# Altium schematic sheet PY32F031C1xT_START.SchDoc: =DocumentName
size A3; Revision: V2.0; SheetNumber: 2; SheetTotal: 2
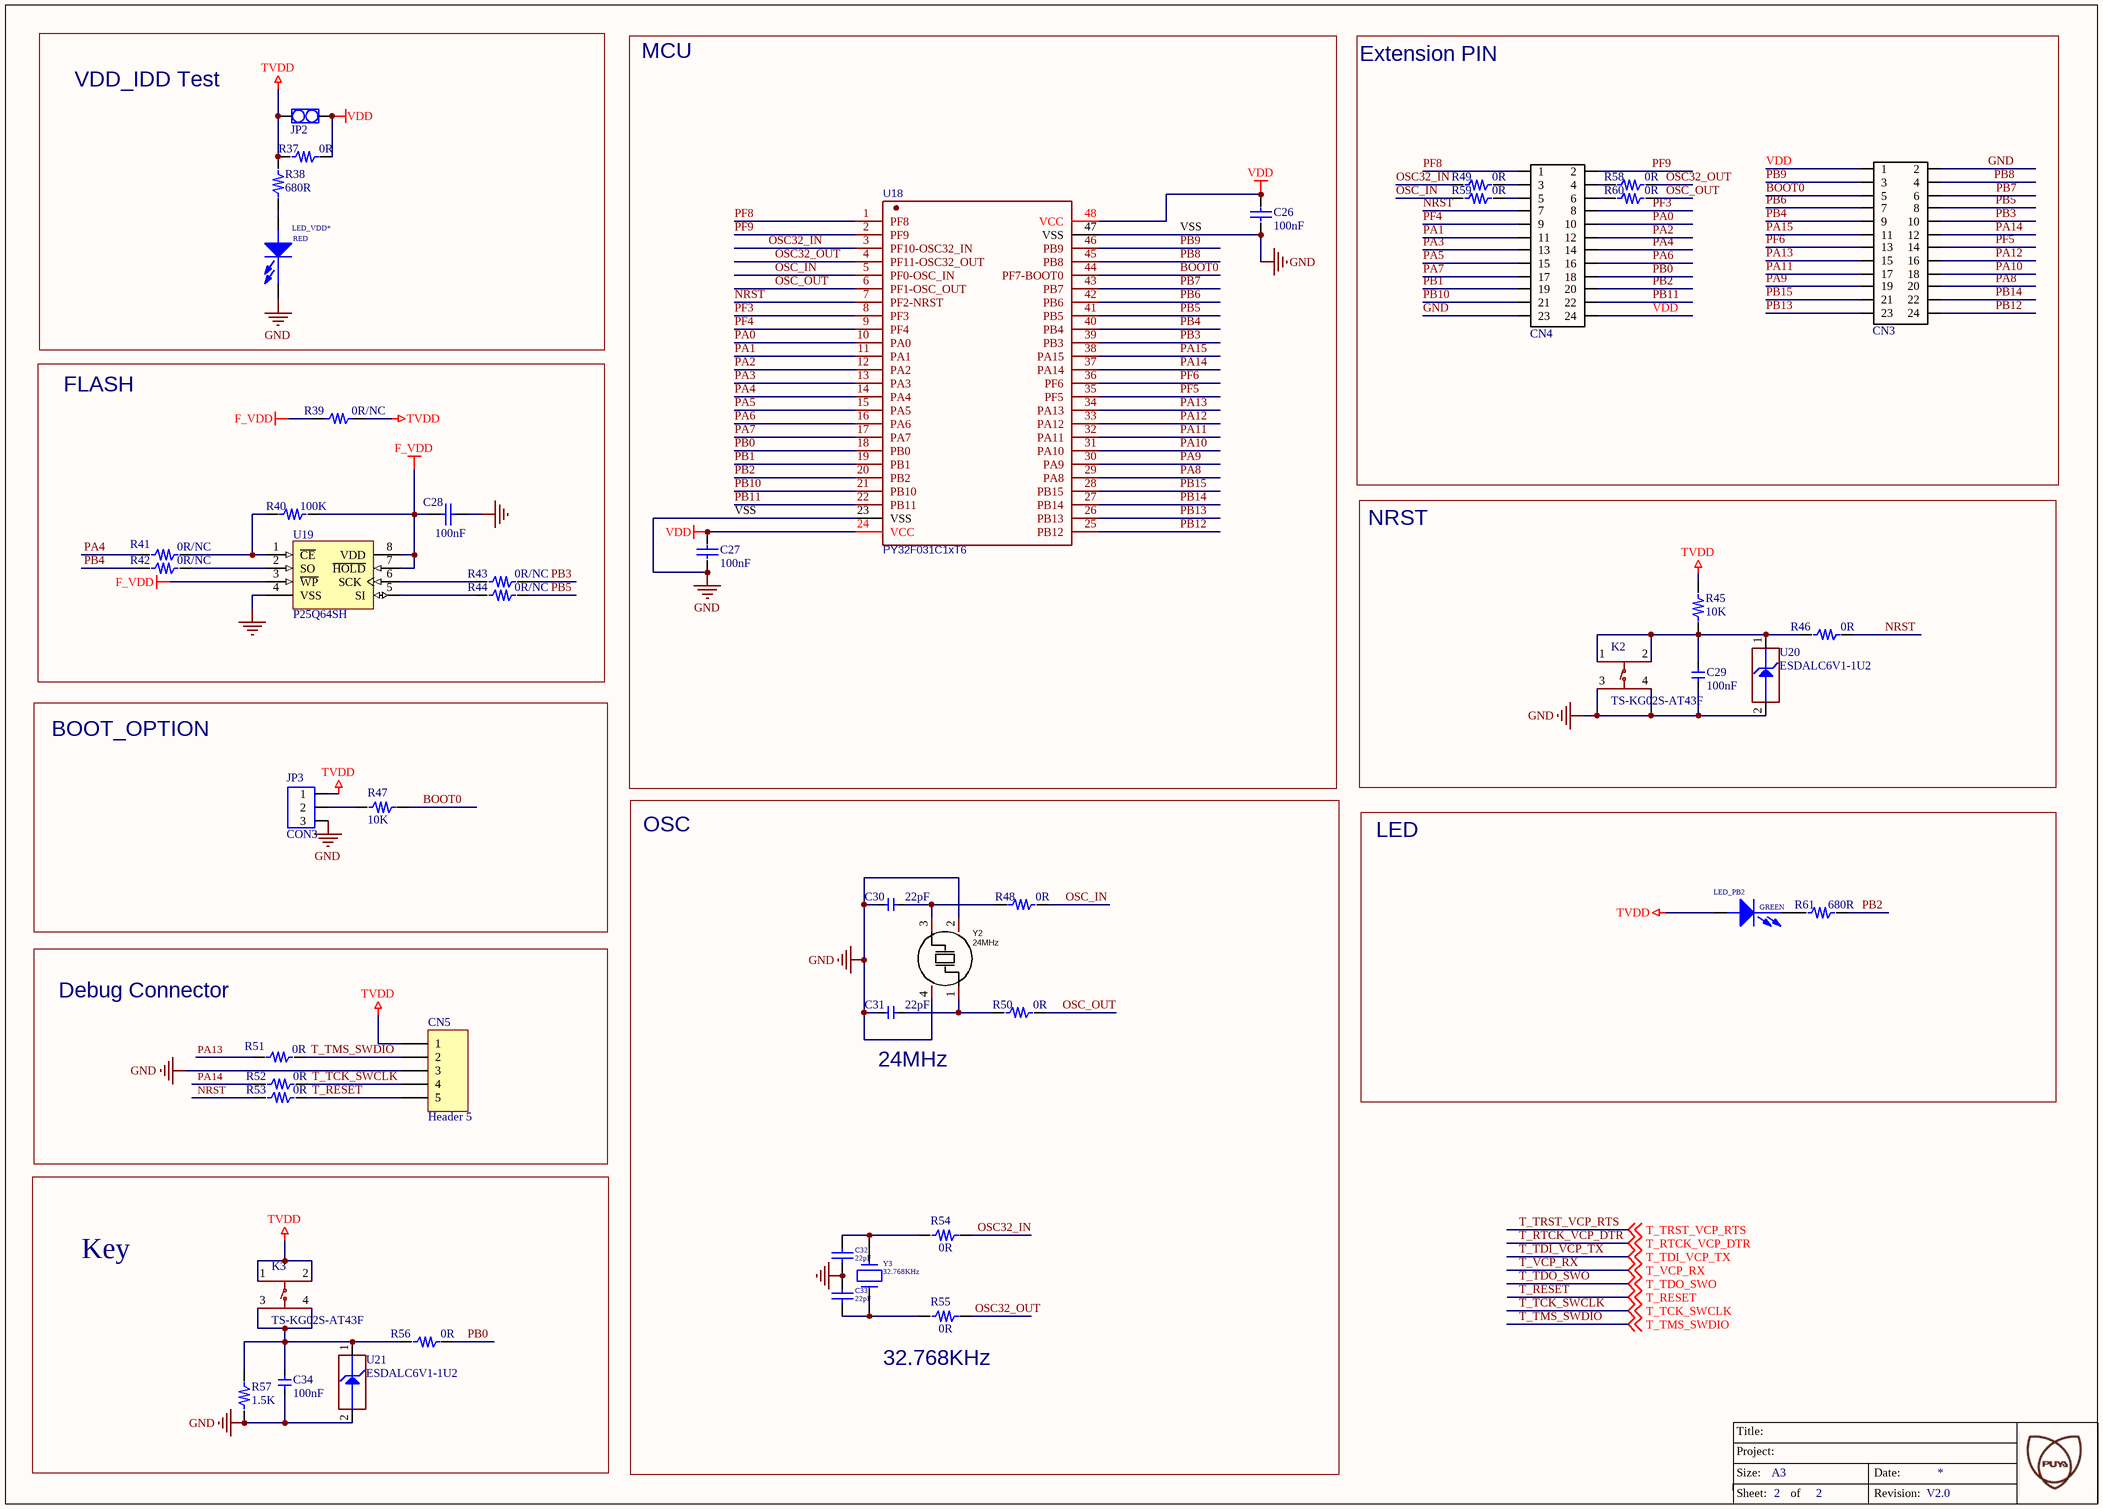
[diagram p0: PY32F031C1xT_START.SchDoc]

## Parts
C26  100nF  [C0603]
C27  100nF  [C0603]
C28  100nF  [C0603]
C29  100nF  [C0603]
C30  22pF  [C0603]
C31  22pF  [C0603]
C32  22pF  [C0603]
C33  22pF  [C0603]
C34  100nF  [C0603]
CN3  CON 2X12  [CON 2X12]  (value not drawn)
CN4  CON 2X12  [CON 2X12]  (value not drawn)
CN5  Header 5  [HDR1X5]
JP2  CON2  [CON2]  (value not drawn)
JP3  CON3  [CON3]
K2  TS-KG02S-AT43F  [SW-SMD_4P-L6.0-W6.0-P4.50-LS8.5]
K3  TS-KG02S-AT43F  [SW-SMD_4P-L6.0-W6.0-P4.50-LS8.5]
LED_PB2  GREEN  [0603_LED]
LED_VDD*  RED  [0603_LED]
R37  0R  [JP2_SMD]
R38  680R  [R0603]
R39  0R/NC  [JP2_SMD]
R40  100K  [R0603]
R41  0R/NC  [JP2_SMD]
R42  0R/NC  [JP2_SMD]
R43  0R/NC  [JP2_SMD]
R44  0R/NC  [JP2_SMD]
R45  10K  [R0603]
R46  0R  [JP2_SMD]
R47  10K  [R0603]
R48  0R  [JP2_SMD]
R49  0R  [JP2_SMD]
R50  0R  [JP2_SMD]
R51  0R  [JP2_SMD]
R52  0R  [JP2_SMD]
R53  0R  [JP2_SMD]
R54  0R  [JP2_SMD]
R55  0R  [JP2_SMD]
R56  0R  [JP2_SMD]
R57  1.5K  [R0603]
R58  0R  [JP2_SMD]
R59  0R  [JP2_SMD]
R60  0R  [JP2_SMD]
R61  680R  [R0603]
U18  PY32F031C1xT6  [LQFP-48_L7.0-W7.0-P0.50-LS9.0-BL]
U19  P25Q64SH  [SOP-8P]
U20  ESDALC6V1-1U2  [ESD_ST0201]
U21  ESDALC6V1-1U2  [ESD_ST0201]
Y2  24MHz  [CRYSTAL-SMD_4P-L3.2-W2.5-BL]
Y3  32.768KHz  [CRYSTAL-SMD_L3.2-W1.5-1]

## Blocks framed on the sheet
VDD_IDD Test: JP2 LED_VDD* R37 R38
MCU: C26 C27 U18
Extension PIN: CN3 CN4 R49 R58-R60
FLASH: C28 R39-R44 U19
NRST: C29 K2 R45 R46 U20
BOOT_OPTION: JP3 R47
LED: LED_PB2 R61
Debug Connector: CN5 R51-R53
Key: C34 K3 R56 R57 U21

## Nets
F_VDD: C28.2 R39.2 R40.2 U19.3(~{WP}) U19.7(~{HOLD}) U19.8(VDD)
GND: C26.2 C27.1 C28.1 C29.1 C30.1 C31.1 C32.2 C33.1 C34.1 CN3.2 CN4.23 CN5.3 JP3.3 K2.3 K2.4 LED_VDD*.2(CATHODE) R57.1 U18.23(VSS) U18.47(VSS) U19.4(VSS) U20.2(GND) U21.2(GND) Y2.2(GND) Y2.4(GND)  [also labelled VSS]
TVDD: CN5.1 JP2.1 JP3.1 K3.1 K3.2 LED_PB2.1(ANODE) R37.1 R38.2 R39.1 R45.1
VDD: C26.1 C27.2 CN3.1 CN4.24 JP2.2 R37.2 U18.24(VCC) U18.48(VCC)
BOOT0: CN3.5 R47.2 U18.44(PF7-BOOT0)
NRST: CN4.7 R46.2 R53.2 U18.7(PF2-NRST)
OSC32_IN: R49.1 R54.1 U18.3(PF10-OSC32_IN)
OSC32_OUT: R55.1 R58.1 U18.4(PF11-OSC32_OUT)
OSC_IN: R48.2 R59.1 U18.5(PF0-OSC_IN)
OSC_OUT: R50.2 R60.1 U18.6(PF1-OSC_OUT)
PA0: CN4.10 U18.10(PA0)
PA1: CN4.11 U18.11(PA1)
PA2: CN4.12 U18.12(PA2)
PA3: CN4.13 U18.13(PA3)
PA4: CN4.14 R41.2 U18.14(PA4)
PA5: CN4.15 U18.15(PA5)
PA6: CN4.16 U18.16(PA6)
PA7: CN4.17 U18.17(PA7)
PA8: CN3.20 U18.29(PA8)
PA9: CN3.19 U18.30(PA9)
PA10: CN3.18 U18.31(PA10)
PA11: CN3.17 U18.32(PA11)
PA12: CN3.16 U18.33(PA12)
PA13: CN3.15 R51.2 U18.34(PA13)
PA14: CN3.12 R52.2 U18.37(PA14)
PA15: CN3.11 U18.38(PA15)
PB0: CN4.18 R56.2 U18.18(PB0)
PB1: CN4.19 U18.19(PB1)
PB2: CN4.20 R61.2 U18.20(PB2)
PB3: CN3.10 R43.1 U18.39(PB3)
PB4: CN3.9 R42.2 U18.40(PB4)
PB5: CN3.8 R44.1 U18.41(PB5)
PB6: CN3.7 U18.42(PB6)
PB7: CN3.6 U18.43(PB7)
PB8: CN3.4 U18.45(PB8)
PB9: CN3.3 U18.46(PB9)
PB10: CN4.21 U18.21(PB10)
PB11: CN4.22 U18.22(PB11)
PB12: CN3.24 U18.25(PB12)
PB13: CN3.23 U18.26(PB13)
PB14: CN3.22 U18.27(PB14)
PB15: CN3.21 U18.28(PB15)
PF3: CN4.8 U18.8(PF3)
PF4: CN4.9 U18.9(PF4)
PF5: CN3.14 U18.35(PF5)
PF6: CN3.13 U18.36(PF6)
PF8: CN4.1 U18.1(PF8)
PF9: CN4.2 U18.2(PF9)
T_RESET: CN5.5 R53.1 ; off-sheet T_RESET
T_TCK_SWCLK: CN5.4 R52.1 ; off-sheet T_TCK_SWCLK
T_TMS_SWDIO: CN5.2 R51.1 ; off-sheet T_TMS_SWDIO
NetC29_2: C29.2 K2.1 K2.2 R45.2 R46.1 U20.1(IO1)
NetC30_2: C30.2 R48.1 Y2.3(OSC2)
NetC31_2: C31.2 R50.1 Y2.1(OSC1)
NetC32_1: C32.1 R54.2 Y3.2
NetC33_2: C33.2 R55.2 Y3.1
NetC34_2: C34.2 K3.3 K3.4 R56.1 R57.2 U21.1(IO1)
NetCN4_3: CN4.3 R49.2
NetCN4_4: CN4.4 R58.2
NetCN4_5: CN4.5 R59.2
NetCN4_6: CN4.6 R60.2
NetJP3_2: JP3.2 R47.1
NetLED_PB2_2: LED_PB2.2(CATHODE) R61.1
NetLED_VDD*_1: LED_VDD*.1(ANODE) R38.1
NetR40_1: R40.1 R41.1 U19.1(~{CE})
NetR42_1: R42.1 U19.2(SO)
NetR43_2: R43.2 U19.6(SCK)
NetR44_2: R44.2 U19.5(SI)

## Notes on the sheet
- OSC
- (near C31) 24MHz
- (near R55) 32.768KHz

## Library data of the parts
C26 C27 C29-C31 C34 = C0603: PCB DECAL: 0603
C28 = 贴片高压陶瓷电容: Capacitor (Semiconductor SIM Model); 器件封装(外观): 0603; Value: 104
C32 C33 = Cap: Capacitor
CN3 CN4 = CON2X12: PCB DECAL: CON5x2
CN5 = Header 5: Header, 5-Pin
JP2 = CON2_DIP
K2 K3 = TS-KG02S-AT43F: Manufacturer: HANBO(汉博); Add into BOM: yes; Circuit: 单刀单掷; Actuator Style: 圆形按钮; Operating Force: 250gf; Switch Length: 6mm; Switch Height: 4.3mm; Strike Gundam: 不带; Contact Current: 50mA; Voltage Rating (DC): 12V; Insulation Resistance: 100MΩ; Actuator/Cap Color: 黑色; Pin Style: 鸥翼型
LED_PB2 LED_VDD* = PDI-E803_Dup1
R37-R61 = R0603: PCB DECAL: 0603
U18 = PY32F031C1xT6: LQFP48; BOM_Manufacturer: PUYA(普冉)
U19 = SST25VF010: Value: SST25VF020B; 器件封装(外观): SOP8
U20 U21 = ESDALC6V1-1U2: ESD protection 6V1; Internal_Part_Number: MCD-00170; Part_Type: Diode; Manufacturer: STMICROELECTRONICS; ECCN_US: EAR99; ECCN_EU: NEC; Provided_By: Subcon; Initial_Board_Reference: MB1274
Y2 = ABM8AIG-24.000MHZ-82Z-T: ±20ppm , 12.5pF , T_use: -40°C~125°C; Manufacturer: ABRACON; Add into BOM: yes; External load capacitor: 8pF; Frequency Stability(Full temperature range): ±50ppm; Equivalent Series Resistance (ESR): 50Ω
Y3 = CRYSTAL_1: Crystal; Value: X503225MSB2GI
